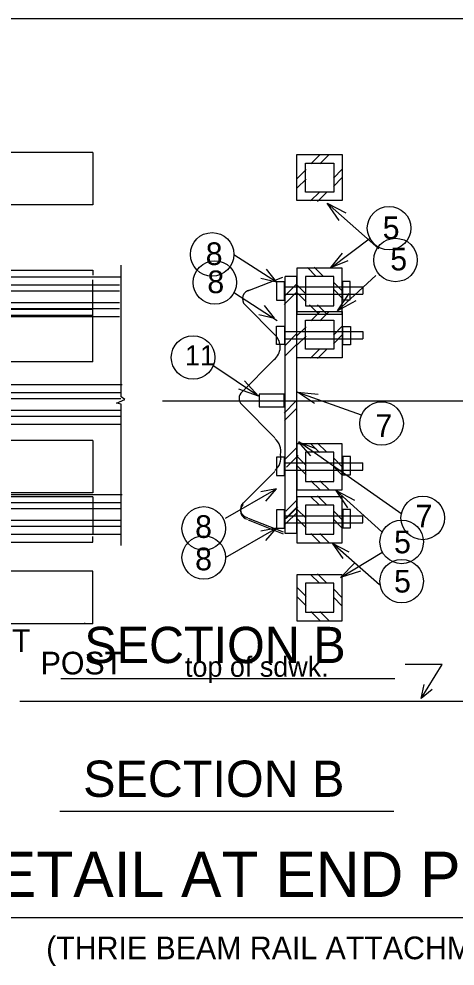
# Model space of a CAD drawing. Extents: x 1509.2 to 1521.3, y 1506 to 1514.6.
# Drawn here: x 1514.148 to 1515.051, y 1511.971 to 1513.931 of the extents above; entities that cross this region are included whole.
import ezdxf

# ---------------------------------------------------------------- set-up
doc = ezdxf.new("R2010")
doc.units = 0
for name, color, linetype in [('Level 1', 7, 'Continuous'), ('Level 2', 7, 'Continuous'), ('Level 3', 7, 'Continuous'), ('Level 4', 7, 'Continuous')]:
    doc.layers.add(name, color=color, linetype=linetype)

msp = doc.modelspace()

# ---------------------------------------------------------------- linework, layer by layer
at = {"layer": 'Level 1'}
msp.add_line((1520.7124, 1513.9308), (1510.2539, 1513.9308), dxfattribs=at)
at = {"layer": 'Level 2'}
msp.add_line((1513.8803, 1512.0718), (1515.6598, 1512.0718), dxfattribs=at)
at = {"layer": 'Level 3'}
for p, q in [((1514.8755, 1513.4774), (1514.7943, 1513.4162)), ((1514.7934, 1513.4163), (1514.8178, 1513.4463)), ((1514.593, 1513.4438), (1514.6815, 1513.3867)), ((1514.7934, 1513.4163), (1514.8291, 1513.4313)), ((1513.0396, 1513.4108), (1514.3013, 1513.4108)), ((1514.3013, 1513.4108), (1514.3013, 1513.4005)), ((1514.3601, 1513.1489), (1514.3601, 1513.4216)), ((1514.8173, 1513.4154), (1514.7235, 1513.4154)), ((1514.7235, 1513.4154), (1514.7235, 1513.32)), ((1514.7634, 1513.3979), (1514.745, 1513.4163)), ((1514.7774, 1513.3988), (1514.7589, 1513.4173)), ((1514.8173, 1513.32), (1514.8173, 1513.4154)), ((1513.4176, 1513.3973), (1514.3592, 1513.3973)), ((1514.3013, 1513.317), (1514.3013, 1513.3909)), ((1514.6218, 1513.3683), (1514.694, 1513.3968)), ((1514.7235, 1513.3983), (1514.6988, 1513.3983)), ((1514.6988, 1512.8663), (1514.6988, 1513.3983)), ((1514.7997, 1513.3979), (1514.7411, 1513.3979)), ((1514.7411, 1513.3979), (1514.7411, 1513.3376)), ((1514.7997, 1513.3376), (1514.7997, 1513.3979)), ((1513.3086, 1513.3684), (1514.3563, 1513.3684)), ((1513.4164, 1513.3807), (1514.3563, 1513.3807)), ((1514.6978, 1513.3575), (1514.7219, 1513.3817)), ((1514.6983, 1513.3765), (1514.8598, 1513.3765)), ((1514.7422, 1513.3617), (1514.7237, 1513.3802)), ((1514.8173, 1513.3533), (1514.7988, 1513.3718)), ((1514.8182, 1513.3673), (1514.7998, 1513.3857)), ((1514.8598, 1513.3765), (1514.8598, 1513.3614)), ((1514.6969, 1513.3398), (1514.7211, 1513.3641)), ((1514.6983, 1513.3614), (1514.8598, 1513.3614)), ((1514.7422, 1513.3458), (1514.7237, 1513.3643)), ((1513.3108, 1513.3442), (1514.3563, 1513.3442)), ((1513.4168, 1513.332), (1514.3563, 1513.332)), ((1514.6162, 1513.3394), (1514.6786, 1513.2768)), ((1514.7411, 1513.3376), (1514.7997, 1513.3376)), ((1514.7682, 1513.3208), (1514.7497, 1513.3393)), ((1514.7848, 1513.3208), (1514.7663, 1513.3393)), ((1514.3013, 1513.317), (1513.1992, 1513.317)), ((1513.4208, 1513.3153), (1514.3563, 1513.3153)), ((1514.7235, 1513.32), (1514.8173, 1513.32)), ((1514.7235, 1512.9402), (1514.7235, 1513.32)), ((1514.6986, 1513.2549), (1514.7228, 1513.2791)), ((1514.6985, 1513.2329), (1514.7227, 1513.2571)), ((1514.6078, 1513.1573), (1514.6766, 1513.2262)), ((1513.4205, 1513.1746), (1514.3621, 1513.1746)), ((1513.4193, 1513.1579), (1514.3592, 1513.1579)), ((1513.3114, 1513.1457), (1514.3592, 1513.1457)), ((1514.3503, 1513.1363), (1514.3677, 1513.1433)), ((1514.3601, 1513.1338), (1514.3503, 1513.1363)), ((1514.3677, 1513.1433), (1514.3601, 1513.1489)), ((1514.3601, 1512.8414), (1514.3601, 1513.1338)), ((1514.6091, 1513.1329), (1514.6778, 1513.0641)), ((1514.6969, 1513.1156), (1514.7211, 1513.1398)), ((1513.3137, 1513.1214), (1514.3592, 1513.1214)), ((1514.6977, 1513.0998), (1514.7218, 1513.1239)), ((1513.4197, 1513.1093), (1514.3592, 1513.1093)), ((1513.4237, 1513.0926), (1514.3592, 1513.0926)), ((1514.7263, 1513.0561), (1514.7516, 1513.0268)), ((1514.7263, 1513.0561), (1514.7623, 1513.0422)), ((1514.9403, 1512.9061), (1514.7271, 1513.0557)), ((1514.6976, 1513.0185), (1514.7218, 1513.0427)), ((1514.7018, 1513.0034), (1514.7259, 1513.0276)), ((1514.6091, 1512.9263), (1514.6778, 1512.9949)), ((1514.3013, 1512.9421), (1513.2014, 1512.9421)), ((1513.4205, 1512.9469), (1514.3621, 1512.9469)), ((1514.3013, 1512.9421), (1514.3013, 1512.8652)), ((1514.7003, 1512.9128), (1514.7244, 1512.9369)), ((1514.8173, 1512.9424), (1514.7235, 1512.9424)), ((1514.7235, 1512.9424), (1514.7235, 1512.847)), ((1514.77, 1512.9247), (1514.7516, 1512.9431)), ((1514.7848, 1512.9256), (1514.7663, 1512.9441)), ((1514.8173, 1512.847), (1514.8173, 1512.9424)), ((1513.3114, 1512.9181), (1514.3592, 1512.9181)), ((1513.4193, 1512.9303), (1514.3592, 1512.9303)), ((1514.7011, 1512.8977), (1514.7253, 1512.9218)), ((1514.7422, 1512.8978), (1514.7237, 1512.9162)), ((1514.7997, 1512.9249), (1514.7411, 1512.9249)), ((1514.7411, 1512.9249), (1514.7411, 1512.8647)), ((1514.7997, 1512.8647), (1514.7997, 1512.9249)), ((1514.6983, 1512.9032), (1514.8598, 1512.9032)), ((1514.7422, 1512.8783), (1514.7237, 1512.8967)), ((1514.8173, 1512.8949), (1514.7988, 1512.9134)), ((1514.8598, 1512.8881), (1514.8598, 1512.9032)), ((1513.3137, 1512.8938), (1514.3592, 1512.8938)), ((1513.4197, 1512.8816), (1514.3592, 1512.8816)), ((1514.5756, 1512.8167), (1514.6815, 1512.8772)), ((1514.6223, 1512.8943), (1514.6947, 1512.8658)), ((1514.6983, 1512.8881), (1514.8598, 1512.8881)), ((1514.8173, 1512.8773), (1514.7988, 1512.8958)), ((1513.4237, 1512.8649), (1514.3592, 1512.8649)), ((1514.3013, 1512.8484), (1514.3013, 1512.8604)), ((1514.7235, 1512.8663), (1514.6988, 1512.8663)), ((1514.7411, 1512.8647), (1514.7997, 1512.8647)), ((1514.7709, 1512.8477), (1514.7525, 1512.8662)), ((1514.7895, 1512.8477), (1514.7711, 1512.8662)), ((1513.0583, 1512.8484), (1514.3013, 1512.8484)), ((1514.7235, 1512.847), (1514.8173, 1512.847)), ((1514.8941, 1512.7598), (1514.7962, 1512.8462)), ((1514.7963, 1512.8463), (1514.8182, 1512.8144)), ((1514.7963, 1512.8463), (1514.8306, 1512.8284)), ((1514.235, 1512.5662), (1514.926, 1512.5662))]:
    msp.add_line(p, q, dxfattribs=at)
for points in [[(1514.649, 1513.3946), (1514.6815, 1513.3867), (1514.6608, 1513.4131)], [(1514.6594, 1512.852), (1514.6815, 1512.8772), (1514.6485, 1512.871)], [(1514.2838, 1512.6812), (1514.2838, 1512.6792)]]:
    msp.add_lwpolyline(points, dxfattribs=at)
for points in [[(1514.6974, 1513.3867), (1514.6815, 1513.3867), (1514.6815, 1513.3488), (1514.6974, 1513.3488)], [(1514.8336, 1513.3876), (1514.8177, 1513.3876), (1514.8177, 1513.3497), (1514.8336, 1513.3497)], [(1514.8344, 1512.9159), (1514.8185, 1512.9159), (1514.8185, 1512.8781), (1514.8344, 1512.8781)], [(1514.6974, 1512.9151), (1514.6815, 1512.9151), (1514.6815, 1512.8772), (1514.6974, 1512.8772)]]:
    msp.add_lwpolyline(points, close=True, dxfattribs=at)
for centre in [(1514.914, 1513.4981), (1514.548, 1513.4438), (1514.9837, 1512.8985), (1514.5306, 1512.8167), (1514.9401, 1512.7676)]:
    msp.add_circle(centre, 0.045, dxfattribs=at)
for centre, radius, start, end in [((1514.6284, 1513.3522), 0.0177, 99.1961, 226.7262), ((1514.655, 1513.2522), 0.0338, 309.2037, 45.7623), ((1514.6214, 1513.1458), 0.0177, 131.5361, 226.7262), ((1514.6563, 1513.0364), 0.0338, 348.371, 50.7963), ((1514.6563, 1513.0228), 0.0338, 309.2037, 11.629), ((1514.6242, 1512.9134), 0.0177, 133.2738, 260.8039)]:
    msp.add_arc(centre, radius, start, end, dxfattribs=at)
at = {"layer": 'Level 4'}
for p, q in [((1514.3013, 1513.6548), (1512.9132, 1513.6548)), ((1514.3013, 1513.6548), (1514.3013, 1513.5465)), ((1514.7235, 1513.555), (1514.7235, 1513.6504)), ((1514.7235, 1513.6504), (1514.8173, 1513.6504)), ((1514.7709, 1513.6498), (1514.7525, 1513.6313)), ((1514.7895, 1513.6498), (1514.7711, 1513.6313)), ((1514.8173, 1513.6504), (1514.8173, 1513.555)), ((1514.7411, 1513.5725), (1514.7411, 1513.6328)), ((1514.7411, 1513.6328), (1514.7997, 1513.6328)), ((1514.7997, 1513.6328), (1514.7997, 1513.5725)), ((1514.7422, 1513.6192), (1514.7237, 1513.6008)), ((1514.8173, 1513.6201), (1514.7988, 1513.6017)), ((1514.8173, 1513.6025), (1514.7988, 1513.584)), ((1514.7422, 1513.5997), (1514.7237, 1513.5813)), ((1514.7997, 1513.5725), (1514.7411, 1513.5725)), ((1514.77, 1513.5728), (1514.7516, 1513.5543)), ((1514.7848, 1513.5718), (1514.7663, 1513.5533)), ((1514.3013, 1513.5465), (1512.9132, 1513.5465)), ((1514.8173, 1513.555), (1514.7235, 1513.555)), ((1514.7863, 1513.5496), (1514.893, 1513.4552)), ((1514.3601, 1513.1489), (1514.3601, 1513.4216)), ((1513.4176, 1513.3973), (1514.3592, 1513.3973)), ((1514.6218, 1513.3683), (1514.694, 1513.3968)), ((1514.7235, 1513.3983), (1514.6988, 1513.3983)), ((1514.6988, 1512.8663), (1514.6988, 1513.3983)), ((1514.7235, 1512.8663), (1514.7235, 1513.3983)), ((1514.8077, 1513.3272), (1514.8869, 1513.4003)), ((1513.3086, 1513.3684), (1514.3563, 1513.3684)), ((1513.4164, 1513.3807), (1514.3563, 1513.3807)), ((1514.6978, 1513.3575), (1514.7219, 1513.3817)), ((1514.5941, 1513.3643), (1514.6826, 1513.3073)), ((1514.6969, 1513.3398), (1514.7211, 1513.3641)), ((1514.3013, 1513.3298), (1513.1049, 1513.3298)), ((1513.3108, 1513.3442), (1514.3563, 1513.3442)), ((1513.4168, 1513.332), (1514.3013, 1513.332)), ((1514.3013, 1513.2215), (1514.3013, 1513.332)), ((1514.6162, 1513.3394), (1514.6786, 1513.2768)), ((1513.4208, 1513.3153), (1514.3563, 1513.3153)), ((1514.7235, 1513.23), (1514.7235, 1513.3254)), ((1514.7235, 1513.3254), (1514.8173, 1513.3254)), ((1514.7411, 1513.2475), (1514.7411, 1513.3078)), ((1514.7411, 1513.3078), (1514.7997, 1513.3078)), ((1514.7709, 1513.3248), (1514.7525, 1513.3063)), ((1514.7895, 1513.3248), (1514.7711, 1513.3063)), ((1514.7997, 1513.3078), (1514.7997, 1513.2475)), ((1514.8173, 1513.3254), (1514.8173, 1513.23)), ((1514.7422, 1513.2942), (1514.7237, 1513.2758)), ((1514.8173, 1513.2951), (1514.7988, 1513.2767)), ((1514.6983, 1513.2843), (1514.8598, 1513.2843)), ((1514.6983, 1513.2693), (1514.8598, 1513.2693)), ((1514.7422, 1513.2747), (1514.7237, 1513.2563)), ((1514.8173, 1513.2775), (1514.7988, 1513.259)), ((1514.8598, 1513.2843), (1514.8598, 1513.2693)), ((1514.8173, 1513.23), (1514.7235, 1513.23)), ((1514.7997, 1513.2475), (1514.7411, 1513.2475)), ((1514.77, 1513.2478), (1514.7516, 1513.2293)), ((1514.7848, 1513.2468), (1514.7663, 1513.2283)), ((1514.3013, 1513.2215), (1513.1077, 1513.2215)), ((1514.6438, 1513.1503), (1514.5516, 1513.2128)), ((1514.6078, 1513.1573), (1514.6766, 1513.2262)), ((1513.4205, 1513.1746), (1514.3621, 1513.1746)), ((1513.4193, 1513.1579), (1514.3592, 1513.1579)), ((1514.7243, 1513.159), (1514.8563, 1513.1121)), ((1513.3114, 1513.1457), (1514.3592, 1513.1457)), ((1514.3503, 1513.1363), (1514.3677, 1513.1433)), ((1514.3601, 1513.1338), (1514.3503, 1513.1363)), ((1514.3677, 1513.1433), (1514.3601, 1513.1489)), ((1514.3601, 1512.8414), (1514.3601, 1513.1338)), ((1514.4451, 1513.1409), (1515.1809, 1513.1409)), ((1514.6091, 1513.1329), (1514.6778, 1513.0641)), ((1514.6969, 1513.1156), (1514.7211, 1513.1398)), ((1513.3137, 1513.1214), (1514.3592, 1513.1214)), ((1514.6977, 1513.0998), (1514.7218, 1513.1239)), ((1513.4197, 1513.1093), (1514.3592, 1513.1093)), ((1513.4237, 1513.0926), (1514.3592, 1513.0926)), ((1514.3013, 1513.059), (1513.1104, 1513.059)), ((1514.3013, 1513.059), (1514.3013, 1512.9507)), ((1514.7848, 1513.035), (1514.7663, 1513.0535)), ((1514.8173, 1513.0518), (1514.7235, 1513.0518)), ((1514.7235, 1513.0518), (1514.7235, 1512.9564)), ((1514.7997, 1513.0343), (1514.7411, 1513.0343)), ((1514.7411, 1513.0343), (1514.7411, 1512.9741)), ((1514.77, 1513.0341), (1514.7516, 1513.0525)), ((1514.7997, 1512.9741), (1514.7997, 1513.0343)), ((1514.8173, 1512.9564), (1514.8173, 1513.0518)), ((1514.7422, 1513.0072), (1514.7237, 1513.0256)), ((1514.8173, 1513.0043), (1514.7988, 1513.0228)), ((1514.6091, 1512.9263), (1514.6778, 1512.9949)), ((1514.6983, 1513.0126), (1514.8598, 1513.0126)), ((1514.6983, 1512.9975), (1514.8598, 1512.9975)), ((1514.7422, 1512.9877), (1514.7237, 1513.0061)), ((1514.8173, 1512.9868), (1514.7988, 1513.0052)), ((1514.8598, 1512.9975), (1514.8598, 1513.0126)), ((1514.7709, 1512.9571), (1514.7525, 1512.9756)), ((1514.7895, 1512.9571), (1514.7711, 1512.9756)), ((1514.5756, 1512.8979), (1514.6815, 1512.9584)), ((1514.7235, 1512.9564), (1514.8173, 1512.9564)), ((1514.7411, 1512.9741), (1514.7997, 1512.9741)), ((1514.8047, 1512.9553), (1514.8991, 1512.87)), ((1514.3013, 1512.9507), (1513.1104, 1512.9507)), ((1513.4205, 1512.9469), (1514.3621, 1512.9469)), ((1513.3114, 1512.9181), (1514.3592, 1512.9181)), ((1513.4193, 1512.9303), (1514.3592, 1512.9303)), ((1514.6977, 1512.8955), (1514.7219, 1512.9197)), ((1514.6223, 1512.8981), (1514.6947, 1512.8696)), ((1514.7001, 1512.886), (1514.7243, 1512.9102)), ((1513.3137, 1512.8938), (1514.3592, 1512.8938)), ((1513.4197, 1512.8816), (1514.3592, 1512.8816)), ((1513.4237, 1512.8649), (1514.3592, 1512.8649)), ((1514.7235, 1512.8663), (1514.6988, 1512.8663)), ((1514.8138, 1512.7755), (1514.8991, 1512.8273)), ((1514.3013, 1512.7882), (1512.9132, 1512.7882)), ((1514.3013, 1512.6798), (1514.3013, 1512.7882)), ((1514.8173, 1512.781), (1514.7235, 1512.781)), ((1514.7235, 1512.781), (1514.7235, 1512.6856)), ((1514.77, 1512.7633), (1514.7516, 1512.7817)), ((1514.7848, 1512.7642), (1514.7663, 1512.7827)), ((1514.8173, 1512.6856), (1514.8173, 1512.781)), ((1514.7997, 1512.7635), (1514.7411, 1512.7635)), ((1514.7411, 1512.7635), (1514.7411, 1512.7033)), ((1514.7997, 1512.7033), (1514.7997, 1512.7635)), ((1514.7422, 1512.7363), (1514.7237, 1512.7548)), ((1514.8173, 1512.7335), (1514.7988, 1512.752)), ((1514.7422, 1512.7168), (1514.7237, 1512.7353)), ((1514.8173, 1512.7159), (1514.7988, 1512.7343)), ((1514.7411, 1512.7033), (1514.7997, 1512.7033)), ((1514.7709, 1512.6863), (1514.7525, 1512.7048)), ((1514.7895, 1512.6863), (1514.7711, 1512.7048)), ((1514.7235, 1512.6856), (1514.8173, 1512.6856)), ((1514.3013, 1512.6798), (1512.9132, 1512.6798)), ((1515.0236, 1512.5953), (1514.9476, 1512.5953)), ((1514.9802, 1512.5248), (1515.0236, 1512.5953)), ((1514.1502, 1512.5193), (1515.2188, 1512.5193)), ((1514.2326, 1512.2921), (1514.9236, 1512.2921))]:
    msp.add_line(p, q, dxfattribs=at)
for points in [[(1514.8107, 1513.5142), (1514.7863, 1513.5496), (1514.8244, 1513.5298)], [(1514.8453, 1513.3478), (1514.8077, 1513.3272), (1514.8313, 1513.3631)], [(1514.6446, 1513.3197), (1514.6771, 1513.3118), (1514.6564, 1513.3382)], [(1514.6152, 1513.1823), (1514.6438, 1513.1503), (1514.6035, 1513.1651)], [(1514.7601, 1513.1353), (1514.7243, 1513.159), (1514.7671, 1513.1548)], [(1514.6594, 1512.9333), (1514.6815, 1512.9584), (1514.6485, 1512.9523)], [(1514.8286, 1512.9197), (1514.8047, 1512.9553), (1514.8426, 1512.9351)], [(1514.8548, 1512.7883), (1514.8138, 1512.7755), (1514.8439, 1512.806)], [(1514.2838, 1512.6812), (1514.2838, 1512.6792)], [(1515.0033, 1512.5437), (1514.9802, 1512.5248), (1514.9867, 1512.5538)]]:
    msp.add_lwpolyline(points, dxfattribs=at)
for points in [[(1514.6974, 1513.2573), (1514.6815, 1513.2573), (1514.6815, 1513.2953), (1514.6974, 1513.2953)], [(1514.8344, 1513.2565), (1514.8185, 1513.2565), (1514.8185, 1513.2943), (1514.8344, 1513.2943)], [(1514.6967, 1513.1544), (1514.6452, 1513.1544), (1514.6452, 1513.1286), (1514.6967, 1513.1286)], [(1514.6974, 1513.0245), (1514.6815, 1513.0245), (1514.6815, 1512.9866), (1514.6974, 1512.9866)], [(1514.8344, 1513.0253), (1514.8185, 1513.0253), (1514.8185, 1512.9875), (1514.8344, 1512.9875)]]:
    msp.add_lwpolyline(points, close=True, dxfattribs=at)
for centre in [(1514.9275, 1513.4321), (1514.5536, 1513.3856), (1514.5085, 1513.2305), (1514.8986, 1513.0938), (1514.5306, 1512.8769), (1514.9401, 1512.8489)]:
    msp.add_circle(centre, 0.045, dxfattribs=at)
for centre, radius, start, end in [((1514.6284, 1513.3522), 0.0177, 99.1961, 226.7262), ((1514.655, 1513.2522), 0.0338, 309.2037, 45.7623), ((1514.6214, 1513.1458), 0.0177, 131.5361, 226.7262), ((1514.6563, 1513.0364), 0.0338, 348.371, 50.7963), ((1514.6242, 1512.9166), 0.0177, 133.2738, 260.8039)]:
    msp.add_arc(centre, radius, start, end, dxfattribs=at)

# ---------------------------------------------------------------- texts
at = {"layer": 'Level 2'}
for s, height, rotation, p in [('DETAIL AT END POST', 0.09375, 360, (1514.01, 1512.1144)), ('(THRIE BEAM RAIL ATTACHMENT)', 0.046875, 0, (1514.2046, 1511.9856))]:
    msp.add_text(s, height=height, rotation=rotation, dxfattribs=at).set_placement(p)
at = {"layer": 'Level 3'}
for s, height, rotation, p in [('5', 0.0469, 360, (1514.9008, 1513.4754)), ('8', 0.0469, 360, (1514.5347, 1513.4217)), ('7', 0.0469, 360, (1514.9688, 1512.879)), ('8', 0.0469, 360, (1514.5128, 1512.7902)), ('5', 0.0469, 360, (1514.9243, 1512.7442)), ('POST', 0.04687, 0, (1514.0016, 1512.6214)), ('SECTION B', 0.075, 0, (1514.2836, 1512.5983))]:
    msp.add_text(s, height=height, rotation=rotation, dxfattribs=at).set_placement(p)
at = {"layer": 'Level 4'}
for s, height, rotation, p in [('5', 0.0469, 360, (1514.9165, 1513.4106)), ('8', 0.0469, 360, (1514.5381, 1513.3635)), ('7', 0.0469, 360, (1514.8859, 1513.0663)), ('8', 0.0469, 360, (1514.5128, 1512.8572)), ('5', 0.0469, 360, (1514.9243, 1512.8254)), ('POST', 0.04687, 0, (1514.1933, 1512.5748)), ('SECTION B', 0.075, 0, (1514.2812, 1512.3215))]:
    msp.add_text(s, height=height, rotation=rotation, dxfattribs=at).set_placement(p)
for s, height, p in [('11', 0.04167, (1514.4918, 1513.214)), ('top of sdwk.', 0.041667, (1514.4918, 1512.5699))]:
    msp.add_text(s, height=height, dxfattribs=at).set_placement(p)

doc.saveas('drawing.dxf')
